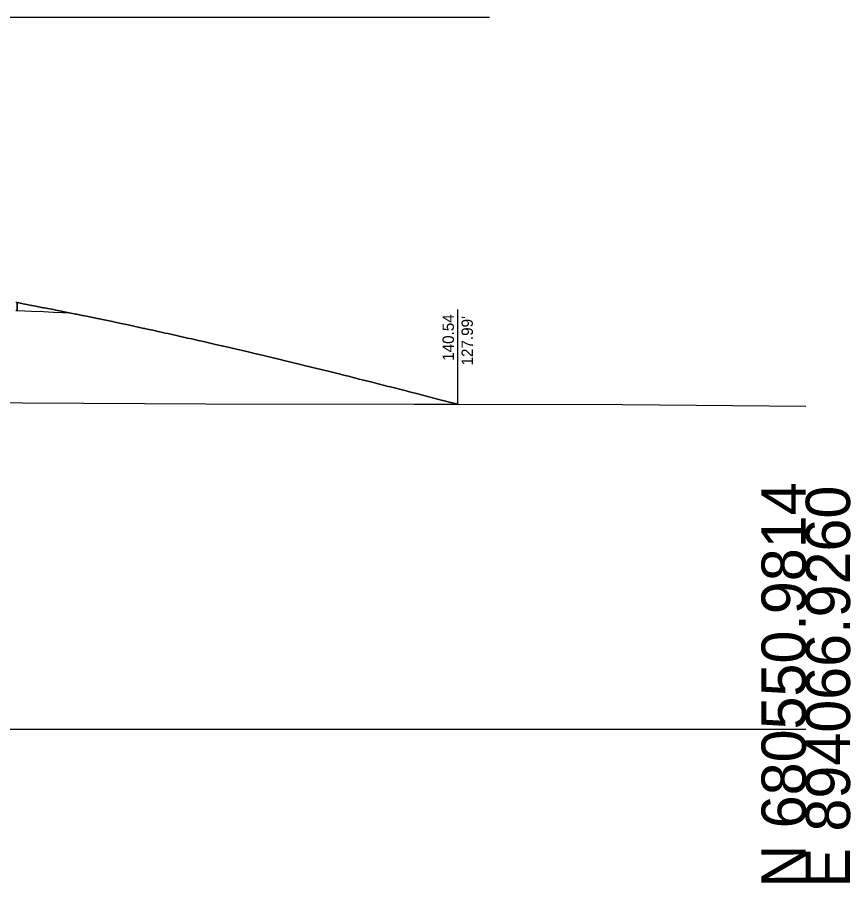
# Model space of a CAD drawing. Extents: x -26 to 4403, y -13 to 9578.
# Drawn here: x 1350.1 to 1402.8, y 6990.3 to 7045 of the extents above; entities that cross this region are included whole.
import ezdxf

# ---------------------------------------------------------------- set-up
doc = ezdxf.new("R2010")
doc.units = 0
for name, color, linetype in [('DTM_X_GROUND', 7, 'Continuous'), ('X_PROFILES_1', 7, 'Continuous'), ('XS_CELL', 7, 'Continuous'), ('XS_M_SHAPES_EARTHWORK', 7, 'Continuous'), ('XS_P_DR_GRAVEL', 7, 'Continuous'), ('XS_P_GROUND', 7, 'Continuous'), ('XS_P_TX_CLEARZONE', 7, 'Continuous')]:
    doc.layers.add(name, color=color, linetype=linetype)

msp = doc.modelspace()

# ---------------------------------------------------------------- linework, layer by layer
at = {"layer": 'DTM_X_GROUND'}
msp.add_lwpolyline([(1172.393, 7016.843), (1201.803, 7015.398), (1214.564, 7014.215), (1224.971, 7013.522), (1232.816, 7013.949), (1243.916, 7015.546), (1247.514, 7017.177), (1252.067, 7016.906), (1267.338, 7018.231), (1284.701, 7020.032), (1288.812, 7020.146), (1295.897, 7020.771), (1296.81, 7020.815), (1306.145, 7020.771), (1331.242, 7020.749), (1362.053, 7020.566), (1388.429, 7020.524), (1400, 7020.43)], dxfattribs=at)
at = {"layer": 'XS_CELL'}
msp.add_line((1250, 7000), (1400, 7000), dxfattribs=at)
at = {"layer": 'XS_M_SHAPES_EARTHWORK'}
msp.add_lwpolyline([(1331.242, 7020.749), (1362.053, 7020.566), (1377.994, 7020.541), (1377.554, 7020.657), (1377.547, 7020.659), (1377.079, 7020.78), (1377.032, 7020.792), (1375.617, 7021.16), (1375.555, 7021.176), (1374.86, 7021.355), (1374.738, 7021.386), (1373.752, 7021.638), (1373.601, 7021.677), (1372.735, 7021.896), (1372.591, 7021.933), (1371.955, 7022.093), (1371.768, 7022.14), (1371.079, 7022.312), (1370.987, 7022.335), (1370.696, 7022.408), (1370.575, 7022.438), (1370.219, 7022.525), (1369.799, 7022.63), (1368.737, 7022.891), (1368.605, 7022.922), (1368.542, 7022.937), (1367.976, 7023.077), (1366.919, 7023.333), (1366.878, 7023.342), (1366.852, 7023.348), (1366.232, 7023.498), (1365.347, 7023.708), (1365.152, 7023.753), (1364.913, 7023.808), (1364.391, 7023.932), (1363.823, 7024.066), (1363.486, 7024.143), (1363.164, 7024.216), (1363.118, 7024.227), (1363.077, 7024.236), (1362.68, 7024.329), (1362.343, 7024.407), (1361.913, 7024.505), (1361.588, 7024.578), (1361.181, 7024.671), (1360.905, 7024.732), (1360.302, 7024.868), (1359.947, 7024.946), (1359.659, 7025.01), (1359.506, 7025.043), (1358.716, 7025.218), (1358.358, 7025.296), (1358.207, 7025.327), (1358.144, 7025.34), (1357.153, 7025.555), (1356.815, 7025.627), (1356.311, 7025.735), (1356.166, 7025.765), (1355.651, 7025.874), (1355.523, 7025.9), (1355.355, 7025.934), (1355.316, 7025.942), (1354.421, 7026.127), (1354.259, 7026.16), (1353.913, 7026.23), (1353.859, 7026.24), (1353.112, 7026.391), (1353.024, 7026.409), (1352.488, 7026.515), (1352.439, 7026.524), (1351.854, 7026.639), (1351.816, 7026.646), (1351.08, 7026.789), (1351.055, 7026.794), (1350.641, 7026.872), (1350.634, 7026.873), (1350.15, 7026.966), (1350.15, 7026.466), (1350.05, 7026.47)], dxfattribs=at)
at = {"layer": 'XS_P_DR_GRAVEL'}
for points in [[(1350.05, 7026.47), (1350.15, 7026.466), (1350.15, 7026.966), (1350.05, 7026.97)], [(1350.15, 7026.466), (1350.634, 7026.446), (1351.055, 7026.43), (1351.816, 7026.399), (1352.439, 7026.374), (1353.024, 7026.351), (1353.383, 7026.336)]]:
    msp.add_lwpolyline(points, dxfattribs=at)
at = {"layer": 'XS_P_GROUND'}
msp.add_line((1250, 7045), (1380, 7045), dxfattribs=at)
msp.add_lwpolyline([(1350.15, 7026.966), (1350.634, 7026.873), (1350.641, 7026.872), (1351.055, 7026.794), (1351.08, 7026.789), (1351.816, 7026.646), (1351.854, 7026.639), (1352.439, 7026.524), (1352.488, 7026.515), (1353.024, 7026.409), (1353.112, 7026.391), (1353.859, 7026.24), (1353.913, 7026.23), (1354.259, 7026.16), (1354.421, 7026.127), (1355.316, 7025.942), (1355.355, 7025.934), (1355.523, 7025.9), (1355.651, 7025.874), (1356.166, 7025.765), (1356.311, 7025.735), (1356.815, 7025.627), (1357.153, 7025.555), (1358.144, 7025.34), (1358.207, 7025.327), (1358.358, 7025.296), (1358.716, 7025.218), (1359.506, 7025.043), (1359.659, 7025.01), (1359.947, 7024.946), (1360.302, 7024.868), (1360.905, 7024.732), (1361.181, 7024.671), (1361.588, 7024.578), (1361.913, 7024.505), (1362.343, 7024.407), (1362.68, 7024.329), (1363.077, 7024.236), (1363.118, 7024.227), (1363.164, 7024.216), (1363.486, 7024.143), (1363.823, 7024.066), (1364.391, 7023.932), (1364.913, 7023.808), (1365.152, 7023.753), (1365.347, 7023.708), (1366.232, 7023.498), (1366.852, 7023.348), (1366.878, 7023.342), (1366.919, 7023.333), (1367.976, 7023.077), (1368.542, 7022.937), (1368.605, 7022.922), (1368.737, 7022.891), (1369.799, 7022.63), (1370.219, 7022.525), (1370.575, 7022.438), (1370.696, 7022.408), (1370.987, 7022.335), (1371.079, 7022.312), (1371.768, 7022.14), (1371.955, 7022.093), (1372.591, 7021.933), (1372.735, 7021.896), (1373.601, 7021.677), (1373.752, 7021.638), (1374.738, 7021.386), (1374.86, 7021.355), (1375.555, 7021.176), (1375.617, 7021.16), (1377.032, 7020.792), (1377.079, 7020.78), (1377.547, 7020.659), (1377.554, 7020.657), (1377.994, 7020.541)], dxfattribs=at)
at = {"layer": 'XS_P_TX_CLEARZONE'}
msp.add_line((1377.994, 7020.541), (1377.994, 7026.541), dxfattribs=at)
msp.add_line((1377.994, 7020.541), (1377.994, 7026.541), dxfattribs=at)
msp.add_line((1377.994, 7020.541), (1377.994, 7026.541), dxfattribs=at)
msp.add_line((1377.994, 7020.541), (1377.994, 7026.541), dxfattribs=at)
msp.add_line((1377.994, 7020.541), (1377.994, 7026.541), dxfattribs=at)
msp.add_line((1377.994, 7020.541), (1377.994, 7026.541), dxfattribs=at)

# ---------------------------------------------------------------- texts
at = {"layer": 'X_PROFILES_1'}
msp.add_text('X', height=0.12, dxfattribs=at).set_placement((1377.954, 7020.481))
at = {"layer": 'XS_CELL'}
for s, p in [('N 680550.9814', (1400, 6990)), ('E 894066.9260', (1402.8, 6990))]:
    msp.add_text(s, height=2.8, rotation=90, dxfattribs=at).set_placement(p)
at = {"layer": 'XS_P_TX_CLEARZONE'}
for s, p in [('140.54', (1377.754, 7023.288)), ('140.54', (1377.754, 7023.288)), ('140.54', (1377.754, 7023.288)), ('140.54', (1377.754, 7023.288)), ('140.54', (1377.754, 7023.288)), ('140.54', (1377.754, 7023.288)), ("127.99'", (1378.954, 7022.993)), ("127.99'", (1378.954, 7022.993)), ("127.99'", (1378.954, 7022.993)), ("127.99'", (1378.954, 7022.993)), ("127.99'", (1378.954, 7022.993)), ("127.99'", (1378.954, 7022.993))]:
    msp.add_text(s, height=0.72, rotation=90, dxfattribs=at).set_placement(p)

doc.saveas('drawing.dxf')
